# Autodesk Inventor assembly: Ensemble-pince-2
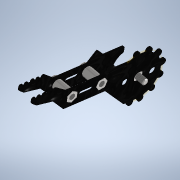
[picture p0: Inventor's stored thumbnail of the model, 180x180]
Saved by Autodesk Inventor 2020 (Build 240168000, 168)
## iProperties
Created: 2021-10
Part Number: Ensemble-pince-2
Document SubType Name: Assembly
Designer: bruno
Author: bruno
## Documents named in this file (4)
- C:\Users\bruno\OneDrive\Bureau\Robot-Inventor\Robot-equillibrage\Ensemble-pince-2.iam
- C:\Users\bruno\OneDrive\Bureau\Robot-Inventor\Robot-equillibrage\Ensemble-doigt-2.iam
- C:\Users\bruno\OneDrive\Bureau\Robot-Inventor\Robot-equillibrage\pince-2.ipt
- C:\Users\bruno\Documents\Inventor\Content Center Files\R2020\fr-FR\ANSI B18.6.7M(01)\ANSI B18.6.7M - M3x0,5 x 5(5).ipt
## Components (5 placed, 3 different names)
1. Ensemble-doigt-2:1 [sub-assembly] — Logement:1, Logement:2
2. pince-2:1 — Logement:1, Logement:2, Logement:5, Logement:6
3. Vis à tête tronconique à empreinte cruciforme - Type IA - Métrique M3x0,5 x 5:1 — Logement:6
4. Vis à tête tronconique à empreinte cruciforme - Type IA - Métrique M3x0,5 x 5:2 — Logement:5
5. Vis à tête tronconique à empreinte cruciforme - Type IA - Métrique M3x0,5 x 5:3
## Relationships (4: Insert 4)
- Logement:1 [Insert]: Ensemble-doigt-2:1 ↔ pince-2:1
- Logement:2 [Insert]: Ensemble-doigt-2:1 ↔ pince-2:1
- Logement:5 [Insert]: pince-2:1 ↔ Vis à tête tronconique à empreinte cruciforme - Type IA - Métrique M3x0,5 x 5:2
- Logement:6 [Insert]: pince-2:1 ↔ Vis à tête tronconique à empreinte cruciforme - Type IA - Métrique M3x0,5 x 5:1
